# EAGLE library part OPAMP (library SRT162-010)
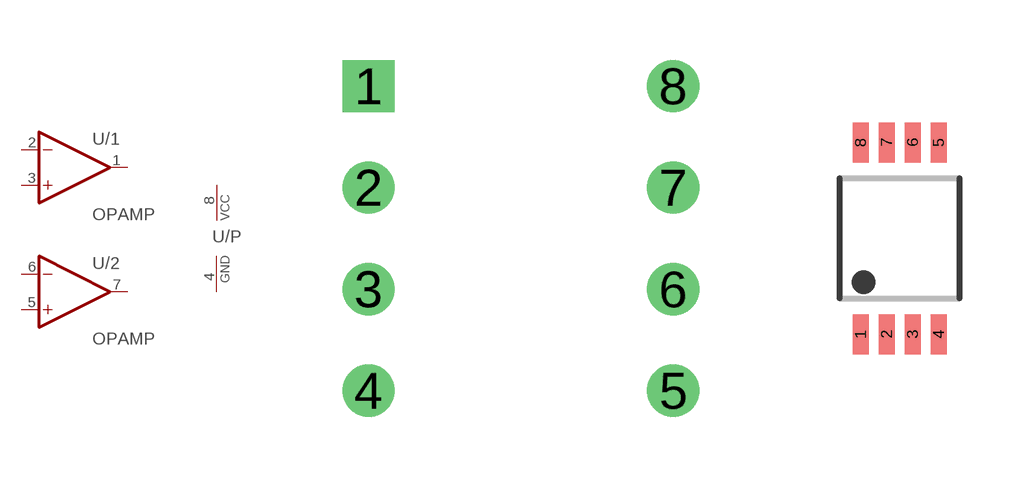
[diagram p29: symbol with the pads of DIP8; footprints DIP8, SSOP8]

Designator prefix U; gates /1=OPAMP /2=OPAMP /P=PWRN

## OPAMP  [DIP8]
1  /1:OUT  pas
2  /1:-IN  in
3  /1:+IN  in
4  /P:GND  pwr
5  /2:+IN  in
6  /2:-IN  in
7  /2:OUT  pas
8  /P:VCC  pwr

## OPAMPSSOP  [SSOP8]
Pads as for DIP8

## OPAMPSOIC  [SOIC8]
Pads as for DIP8

## Footprint DIP8 (pad centres in mm)
drill 0.8 square: 1 -3.81,3.81
drill 0.8 round: 2 -3.81,1.27; 3 -3.81,-1.27; 4 -3.81,-3.81; 5 3.81,-3.81; 6 3.81,-1.27; 7 3.81,1.27; 8 3.81,3.81

## Footprint SSOP8 (pad centres in mm)
smd 0.4 x 1: 1 -0.975,-2.4; 2 -0.325,-2.4; 3 0.325,-2.4; 4 0.975,-2.4; 5 0.975,2.4; 6 0.325,2.4; 7 -0.325,2.4; 8 -0.975,2.4

## Footprint SOIC8 (pad centres in mm)
smd 0.5 x 2.2: 1 -1.905,-3.154; 2 -0.645,-3.154; 3 0.625,-3.154; 4 1.895,-3.154; 5 1.905,3.154; 6 0.635,3.154; 7 -0.635,3.154; 8 -1.905,3.154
